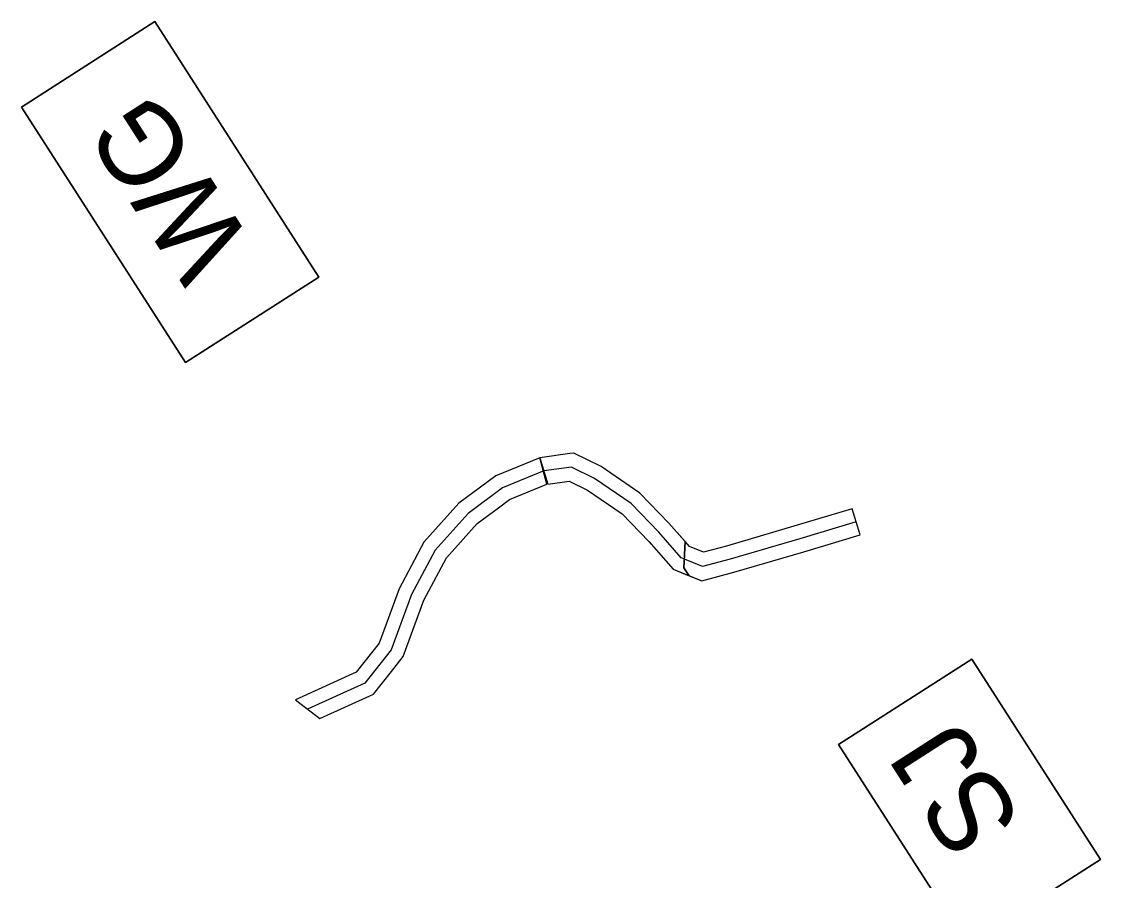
# Model space of a CAD drawing. Extents: x 474218 to 481634, y 484357 to 504997.
# Drawn here: x 477587.8 to 477786, y 499246.9 to 499404.7 of the extents above; entities that cross this region are included whole.
import ezdxf

# ---------------------------------------------------------------- set-up
doc = ezdxf.new("R2010")
doc.units = 0
for name, color, linetype in [('Exist Hydro Jurisdictional Stream or Body of Water', 7, 'Continuous'), ('Old_Level_30', 7, 'Continuous'), ('Prop Earthen Structure Impacts In Surface Waters Hatching CELL', 7, 'Continuous'), ('Prop Grid Mask', 7, 'Continuous'), ('Scratch_Level_4', 7, 'Continuous'), ('Scratch_Level_6', 7, 'Continuous'), ('Temp Earthen Structure Impacts In Surface Waters Hatching CELL', 7, 'Continuous')]:
    doc.layers.add(name, color=color, linetype=linetype)

msp = doc.modelspace()

# ---------------------------------------------------------------- linework, layer by layer
at = {"layer": 'Exist Hydro Jurisdictional Stream or Body of Water'}
msp.add_lwpolyline([(477761.5, 499235.07), (477737.89, 499271.87), (477762.37, 499287.58), (477785.98, 499250.77)], close=True, dxfattribs=at)
at = {"layer": 'Old_Level_30'}
msp.add_lwpolyline([(477617.89, 499342.03), (477587.77, 499388.98), (477612.25, 499404.69), (477642.37, 499357.74)], close=True, dxfattribs=at)
at = {"layer": 'Prop Earthen Structure Impacts In Surface Waters Hatching CELL'}
msp.add_lwpolyline([(477741.83, 499310.4), (477740.4, 499315.19), (477717.26, 499308.34), (477713.05, 499307.2), (477710.46, 499308.27), (477706.69, 499312.56), (477701.38, 499318.07), (477694.27, 499322.93), (477689.24, 499325.43), (477688.48, 499325.32), (477682.99, 499324.57), (477684.43, 499319.72), (477688.39, 499320.27), (477691.74, 499318.61), (477698.13, 499314.23), (477703.01, 499309.17), (477707.47, 499304.09), (477712.72, 499301.94), (477718.62, 499303.53), (477731.46, 499307.3), (477741.83, 499310.4)], dxfattribs=at)
at = {"layer": 'Prop Grid Mask'}
for points in [[(477642.37, 499357.74), (477612.25, 499404.69), (477587.77, 499388.98), (477617.89, 499342.03)], [(477785.98, 499250.77), (477762.37, 499287.58), (477737.89, 499271.87), (477761.5, 499235.07)]]:
    msp.add_lwpolyline(points, close=True, dxfattribs=at)
at = {"layer": 'Scratch_Level_4'}
msp.add_lwpolyline([(477741.83, 499310.4), (477740.4, 499315.19), (477717.26, 499308.34), (477713.05, 499307.2), (477710.46, 499308.27), (477706.69, 499312.56), (477701.38, 499318.07), (477694.27, 499322.93), (477689.24, 499325.43), (477688.48, 499325.32), (477682.99, 499324.57), (477684.43, 499319.72), (477688.39, 499320.27), (477691.74, 499318.61), (477698.13, 499314.23), (477703.01, 499309.17), (477707.47, 499304.09), (477712.72, 499301.94), (477718.62, 499303.53), (477731.46, 499307.3)], close=True, dxfattribs=at)
for points in [[(477683.71, 499322.16), (477676.15, 499319.06), (477669.8, 499314.34), (477663.76, 499307.6), (477659.41, 499299.43), (477655.69, 499289.27), (477650.83, 499283.13), (477640.33, 499278.38)], [(477709.55, 499305.94), (477708.97, 499306.18), (477704.85, 499310.86), (477699.75, 499316.15), (477693.01, 499320.77), (477688.82, 499322.85), (477683.71, 499322.14)], [(477741.11, 499312.8), (477730.75, 499309.69), (477717.94, 499305.93), (477712.89, 499304.57), (477709.55, 499305.94)]]:
    msp.add_lwpolyline(points, dxfattribs=at)
at = {"layer": 'Scratch_Level_6'}
for p, q in [((477709.68, 499309.16), (477706.69, 499312.56)), ((477709.47, 499304.32), (477709.68, 499309.16)), ((477709.68, 499309.16), (477709.47, 499304.32)), ((477710.42, 499302.88), (477709.47, 499304.32)), ((477709.47, 499304.32), (477710.42, 499302.88))]:
    msp.add_line(p, q, dxfattribs=at)
for points in [[(477706.69, 499312.56), (477701.38, 499318.07), (477694.27, 499322.93), (477689.24, 499325.43), (477688.48, 499325.32), (477682.99, 499324.57), (477684.43, 499319.72), (477688.39, 499320.27), (477691.74, 499318.61), (477698.13, 499314.23), (477703.01, 499309.17), (477707.47, 499304.09), (477710.42, 499302.88)], [(477710.42, 499302.88), (477712.72, 499301.94), (477718.62, 499303.53), (477731.46, 499307.3), (477741.83, 499310.4), (477740.4, 499315.19), (477717.26, 499308.34), (477713.05, 499307.2), (477710.46, 499308.27), (477709.68, 499309.16)]]:
    msp.add_lwpolyline(points, dxfattribs=at)
at = {"layer": 'Temp Earthen Structure Impacts In Surface Waters Hatching CELL'}
msp.add_line((477638.09, 499280.1), (477642.58, 499276.65), dxfattribs=at)
for points in [[(477682.99, 499324.57), (477674.91, 499321.25), (477668.11, 499316.2), (477661.69, 499309.04), (477657.12, 499300.45), (477653.48, 499290.51), (477649.24, 499285.16), (477638.09, 499280.1)], [(477642.58, 499276.65), (477652.41, 499281.11), (477655.72, 499285.29), (477657.9, 499288.03), (477661.69, 499298.41), (477665.82, 499306.16), (477671.5, 499312.48), (477675.4, 499315.38), (477677.39, 499316.87), (477684.3, 499319.7), (477682.99, 499324.57)]]:
    msp.add_lwpolyline(points, dxfattribs=at)

# ---------------------------------------------------------------- texts
at = {"layer": 'Exist Hydro Jurisdictional Stream or Body of Water'}
msp.add_text('SJ', height=15, rotation=122.6822, dxfattribs=at).set_placement((477771.98, 499257.8))
at = {"layer": 'Old_Level_30'}
msp.add_text('WG', height=15, rotation=122.6822, dxfattribs=at).set_placement((477630.49, 499363.6))

doc.saveas('drawing.dxf')
